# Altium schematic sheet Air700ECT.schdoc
size 297 x 209 mm; Symbol: Drawing-Symbol_A4; Company: 嘉立创EDA; Version: V1.0; Page Size: A4; @Project Name: Air700ECT; @Update Date: 2025-12-03; @Create Date: 2025-12-03; Device: Drawing-Symbol_A4; @Page Name: P1; @Create Time: 16:24:23; @Page Count: 1; @Page No: 1; @Schematic Name: Schematic1; @Update Time: 16:24:23; @Assembly Variant: Basic; Title Block Position: 3; Size: A4; Width: 1170; Height: 825; Region Start: 1; X Region Count: 6; Y Region Count: 4; Blade Width: 10
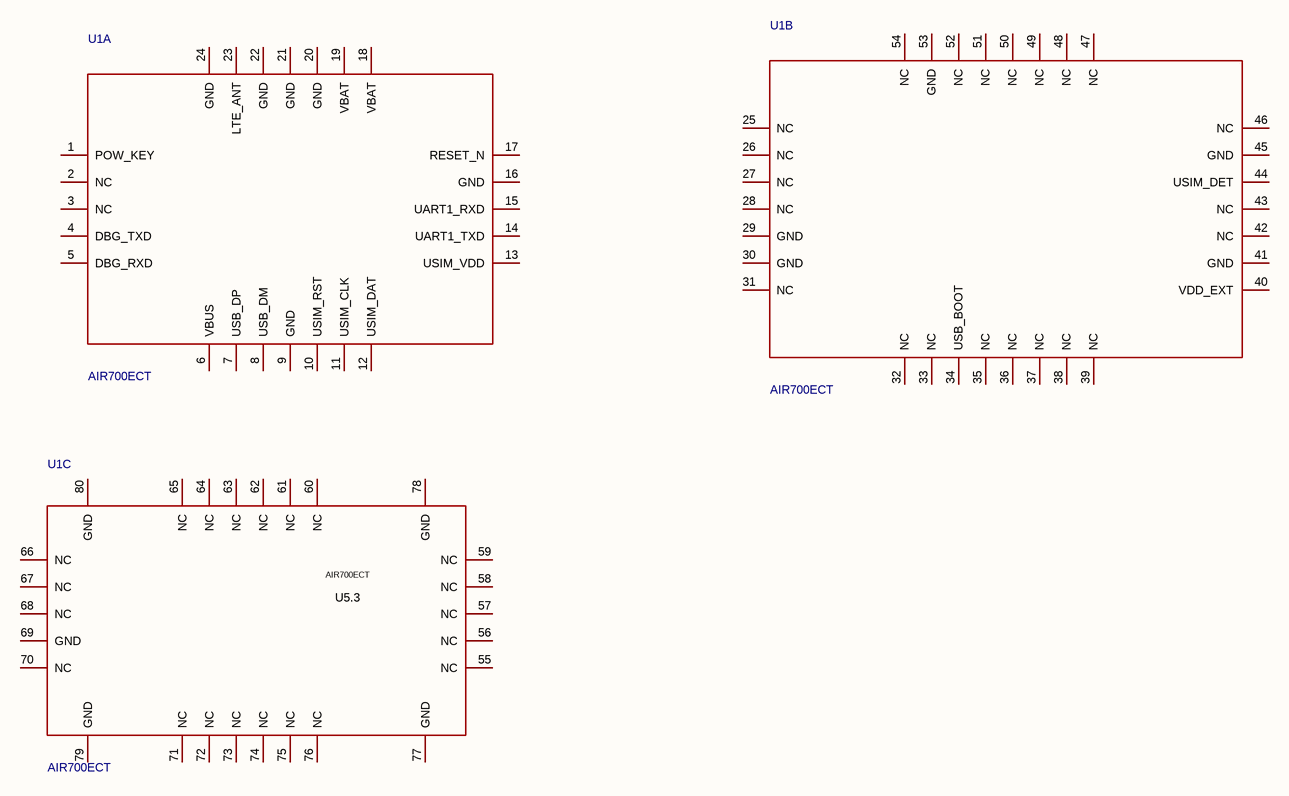
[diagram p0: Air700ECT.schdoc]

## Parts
U1  AIR700ECT  [AIR700ECT]  (parts A,B,C of 3)

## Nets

Not connected (* = marked no-connect by the designer): U1 1(POW_KEY) 2(NC) 3(NC) 4(DBG_TXD) 5(DBG_RXD) 6(VBUS) 7(USB_DP) 8(USB_DM) 9(GND) 10(USIM_RST) 11(USIM_CLK) 12(USIM_DAT) 13(USIM_VDD) 14(UART1_TXD) 15(UART1_RXD) 16(GND) 17(RESET_N) 18(VBAT) 19(VBAT) 20(GND) 21(GND) 22(GND) 23(LTE_ANT) 24(GND) 25(NC) 26(NC) 27(NC) 28(NC) 29(GND) 30(GND) 31(NC) 32(NC) 33(NC) 34(USB_BOOT) 35(NC) 36(NC) 37(NC) 38(NC) 39(NC) 40(VDD_EXT) 41(GND) 42(NC) 43(NC) 44(USIM_DET) 45(GND) 46(NC) 47(NC) 48(NC) 49(NC) 50(NC) 51(NC) 52(NC) 53(GND) 54(NC) 55(NC) 56(NC) 57(NC) 58(NC) 59(NC) 60(NC) 61(NC) 62(NC) 63(NC) 64(NC) 65(NC) 66(NC) 67(NC) 68(NC) 69(GND) 70(NC) 71(NC) 72(NC) 73(NC) 74(NC) 75(NC) 76(NC) 77(GND) 78(GND) 79(GND) 80(GND)

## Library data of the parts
U1 = AIR700ECT: Relevance: []; AddInBom: yes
